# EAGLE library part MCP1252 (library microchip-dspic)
Positive-Regulated Charge Pump (3.3x5.0)
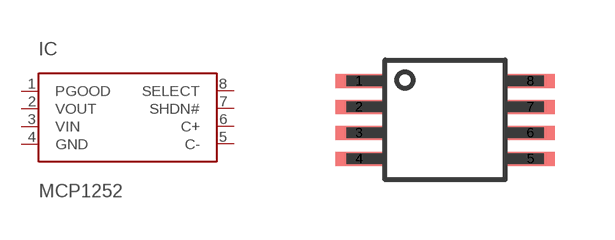
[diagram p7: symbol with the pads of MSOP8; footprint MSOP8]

Designator prefix IC

## MCP1252  [MSOP8]
1  PGOOD  oc
2  VOUT  sup
3  VIN  pwr
4  GND  pwr
5  C-  pas
6  C+  pas
7  SHDN#  in
8  SELECT  in

## Footprint MSOP8 (pad centres in mm)
Micro Small Outline Package
smd 1.2 x 0.35: 1 -2.145,0.975; 2 -2.145,0.325; 3 -2.145,-0.325; 4 -2.145,-0.975; 5 2.145,-0.975; 6 2.145,-0.325; 7 2.145,0.325; 8 2.145,0.975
